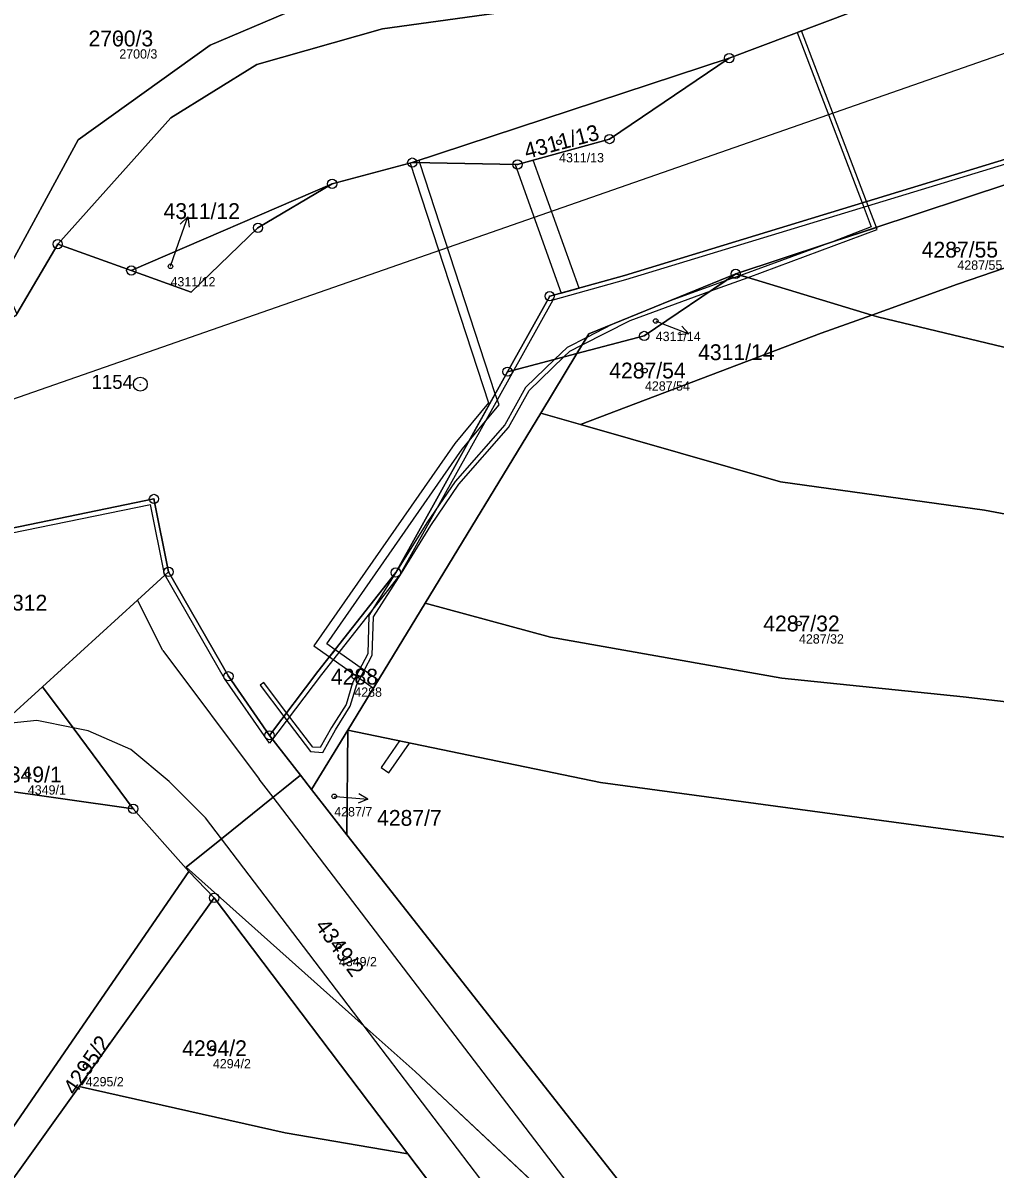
# Model space of a CAD drawing. Extents: x -739214 to -733252, y -1147612 to -1142842.
# Drawn here: x -737846.7 to -737742.2, y -1146463.6 to -1146340.4 of the extents above; entities that cross this region are included whole.
import ezdxf

# ---------------------------------------------------------------- set-up
doc = ezdxf.new("R2010")
doc.units = 0
for name, color, linetype in [('Definiční body', 7, 'Continuous'), ('Hranice parcel', 7, 'Continuous'), ('Parcelní čísla', 7, 'Continuous'), ('Polygon parcely', 7, 'Continuous'), ('Pop  PČ popisy', 7, 'Continuous'), ('Poz předměty', 7, 'Continuous'), ('Vnitřní kresba', 7, 'Continuous'), ('Věcná břemena k části', 7, 'Continuous'), ('Značky bodu BP', 7, 'Continuous')]:
    doc.layers.add(name, color=color, linetype=linetype)

msp = doc.modelspace()

# ---------------------------------------------------------------- linework, layer by layer
at = {"layer": 'Definiční body'}
for centre in [(-737836.38, -1146342.06), (-737789.07, -1146353.22), (-737746.22, -1146364.77), (-737830.87, -1146366.56), (-737778.67, -1146372.44), (-737779.83, -1146377.77), (-737763.26, -1146404.97), (-737811.1, -1146410.69), (-737846.22, -1146421.21), (-737813.26, -1146423.56), (-737812.76, -1146439.68), (-737826.31, -1146450.65), (-737839.99, -1146452.59)]:
    msp.add_circle(centre, 0.25, dxfattribs=at)
at = {"layer": 'Hranice parcel'}
for p, q in [((-737804.86, -1146355.41), (-737770.76, -1146344.17)), ((-737813.48, -1146357.69), (-737804.86, -1146355.41)), ((-737835.09, -1146367.01), (-737813.48, -1146357.69)), ((-737770.07, -1146367.38), (-737740.56, -1146357.63)), ((-737847.41, -1146371.67), (-737843.01, -1146364.17)), ((-737843.01, -1146364.17), (-737835.09, -1146367.01)), ((-737755.42, -1146371.8), (-737770.07, -1146367.38)), ((-737754.68, -1146372.02), (-737755.42, -1146371.8)), ((-737787.15, -1146375.94), (-737794.61, -1146377.89)), ((-737791.04, -1146382.34), (-737787.15, -1146375.94)), ((-737803.48, -1146402.77), (-737791.04, -1146382.34)), ((-737786.78, -1146383.56), (-737791.04, -1146382.34)), ((-737786.78, -1146383.56), (-737765.25, -1146389.72)), ((-737831.08, -1146399.42), (-737832.65, -1146391.58)), ((-737831.08, -1146399.42), (-737824.64, -1146410.65)), ((-737811.81, -1146416.45), (-737803.48, -1146402.77)), ((-737824.64, -1146410.65), (-737820.22, -1146417)), ((-737820.22, -1146417), (-737816.9, -1146421.29)), ((-737815.7, -1146422.84), (-737811.81, -1146416.45)), ((-737811.89, -1146427.69), (-737811.81, -1146416.45)), ((-737816.9, -1146421.29), (-737815.7, -1146422.84)), ((-737811.89, -1146427.69), (-737815.7, -1146422.84)), ((-737828.9, -1146431.66), (-737834.88, -1146424.9)), ((-737826.18, -1146434.48), (-737828.9, -1146431.66)), ((-737826.18, -1146434.48), (-737840.71, -1146454.78)), ((-737805.33, -1146462), (-737826.18, -1146434.48)), ((-737804.56, -1146453.15), (-737782.6, -1146473.73)), ((-737786.69, -1146486.61), (-737805.33, -1146462))]:
    msp.add_line(p, q, dxfattribs=at)
for points in [[(-737541.62, -1146282.04), (-737556.86, -1146290), (-737606.78, -1146309.22), (-737682.42, -1146335.31), (-737733.78, -1146352.83), (-737782.04, -1146367.55), (-737790.08, -1146369.77), (-737794.61, -1146377.89)], [(-737770.76, -1146344.17), (-737757.42, -1146339.15), (-737761.18, -1146335.83), (-737732.08, -1146310)], [(-737801.34, -1146332.03), (-737826.62, -1146342.79), (-737840.79, -1146352.96), (-737849.01, -1146368.07)], [(-737843.01, -1146364.17), (-737830.84, -1146350.59), (-737821.57, -1146344.85), (-737808.05, -1146341.01), (-737791.14, -1146338.69), (-737786.28, -1146336.05)], [(-737804.86, -1146355.41), (-737793.54, -1146355.61), (-737783.64, -1146352.87), (-737770.76, -1146344.17)], [(-737835.09, -1146367.01), (-737828.64, -1146369.33), (-737821.46, -1146362.41), (-737813.48, -1146357.69)], [(-737723.18, -1146360.59), (-737746.21, -1146368.48), (-737755.42, -1146371.8)], [(-737770.07, -1146367.38), (-737785.86, -1146373.83), (-737787.15, -1146375.94)], [(-737787.15, -1146375.94), (-737779.91, -1146374.05), (-737770.07, -1146367.38)], [(-737755.42, -1146371.8), (-737760.88, -1146373.76), (-737786.78, -1146383.56)], [(-737551.77, -1146412.44), (-737658.53, -1146391.6), (-737713.59, -1146381.89), (-737754.68, -1146372.02)], [(-737794.61, -1146377.89), (-737806.64, -1146399.5), (-737815.02, -1146410.14), (-737820.22, -1146417)], [(-737765.25, -1146389.72), (-737743.32, -1146392.8), (-737722.45, -1146396.68)], [(-737832.65, -1146391.58), (-737849.12, -1146394.96), (-737851.76, -1146395.5)], [(-737844.65, -1146411.77), (-737834.41, -1146402.45), (-737831.08, -1146399.42)], [(-737724.99, -1146415.27), (-737745.59, -1146412.86), (-737765.12, -1146410.86), (-737790, -1146406.44), (-737803.48, -1146402.77)], [(-737844.65, -1146411.77), (-737849.06, -1146415.79), (-737860.78, -1146426.46)], [(-737834.88, -1146424.9), (-737841.35, -1146416.2), (-737844.65, -1146411.77)], [(-737331.59, -1146506.62), (-737376.05, -1146494.4), (-737398.38, -1146490.12), (-737436.24, -1146484.9), (-737462.76, -1146481.83), (-737505.69, -1146475.14), (-737536.46, -1146468.45), (-737570.21, -1146459.63), (-737667.64, -1146439.85), (-737707.45, -1146432.51), (-737784.63, -1146422.07), (-737811.81, -1146416.45)], [(-737816.9, -1146421.29), (-737818.76, -1146422.79), (-737819.84, -1146423.66), (-737825.39, -1146428.13), (-737829.19, -1146431.19), (-737810.05, -1146448.26), (-737804.56, -1146453.15)], [(-737834.88, -1146424.9), (-737850.3, -1146422.72), (-737860.78, -1146426.46)], [(-737781.39, -1146466.64), (-737782.68, -1146464.89), (-737811.89, -1146427.69)], [(-737828.9, -1146431.66), (-737851.76, -1146464.79), (-737854.56, -1146467.91)], [(-737840.71, -1146454.78), (-737849.54, -1146467.11), (-737851.95, -1146469.79)], [(-737840.71, -1146454.78), (-737818.54, -1146459.73), (-737805.33, -1146462)]]:
    msp.add_lwpolyline(points, dxfattribs=at)
at = {"layer": 'Polygon parcely'}
for points in [[(-737851.76, -1146395.5), (-737849.12, -1146394.96), (-737832.65, -1146391.58), (-737831.08, -1146399.42), (-737824.64, -1146410.65), (-737820.22, -1146417), (-737815.02, -1146410.14), (-737806.64, -1146399.5), (-737794.61, -1146377.89), (-737790.08, -1146369.77), (-737782.04, -1146367.55), (-737733.78, -1146352.83), (-737682.42, -1146335.31), (-737606.78, -1146309.22), (-737556.86, -1146290), (-737541.62, -1146282.04), (-737519.96, -1146274.64), (-737515.86, -1146273.22), (-737508.96, -1146270.82), (-737487.35, -1146263.31), (-737469.84, -1146257.23), (-737448.4, -1146249.68), (-737443.72, -1146247.99)], [(-737733.73, -1146289.74), (-737746.11, -1146300.83), (-737747.42, -1146302), (-737757.62, -1146311.04), (-737758.73, -1146312.07), (-737772.14, -1146324.45), (-737773.11, -1146325.27), (-737785.1, -1146335.41), (-737786.28, -1146336.05), (-737791.14, -1146338.69), (-737808.05, -1146341.01), (-737821.57, -1146344.85), (-737830.84, -1146350.59), (-737843.01, -1146364.17), (-737835.09, -1146367.01), (-737813.48, -1146357.69), (-737804.86, -1146355.41), (-737770.76, -1146344.17), (-737757.42, -1146339.15), (-737761.18, -1146335.83), (-737732.08, -1146310)], [(-737732.08, -1146310), (-737761.18, -1146335.83), (-737757.42, -1146339.15), (-737770.76, -1146344.17), (-737783.64, -1146352.87), (-737793.54, -1146355.61), (-737804.86, -1146355.41), (-737813.48, -1146357.69), (-737821.46, -1146362.41), (-737828.64, -1146369.33), (-737835.09, -1146367.01), (-737843.01, -1146364.17), (-737847.41, -1146371.67), (-737847.53, -1146371.89), (-737858.37, -1146378.37), (-737869.23, -1146382.14), (-737887.99, -1146388.67), (-737903.08, -1146393.94), (-737917.17, -1146398.85), (-737950.33, -1146410.42), (-738012.69, -1146432)], [(-737782.6, -1146473.73), (-737804.56, -1146453.15), (-737810.05, -1146448.26), (-737829.19, -1146431.19), (-737825.39, -1146428.13), (-737819.84, -1146423.66), (-737818.76, -1146422.79), (-737816.9, -1146421.29), (-737820.22, -1146417), (-737824.64, -1146410.65), (-737831.08, -1146399.42), (-737834.41, -1146402.45), (-737844.65, -1146411.77), (-737841.35, -1146416.2), (-737834.88, -1146424.9), (-737828.9, -1146431.66), (-737826.18, -1146434.48), (-737805.33, -1146462), (-737786.69, -1146486.61)], [(-737601.76, -1146439.15), (-737682.84, -1146423.31), (-737724.99, -1146415.27), (-737745.59, -1146412.86), (-737765.12, -1146410.86), (-737790, -1146406.44), (-737803.48, -1146402.77), (-737811.81, -1146416.45), (-737784.63, -1146422.07), (-737707.45, -1146432.51), (-737667.64, -1146439.85), (-737570.21, -1146459.63)], [(-737570.21, -1146459.63), (-737667.64, -1146439.85), (-737707.45, -1146432.51), (-737784.63, -1146422.07), (-737811.81, -1146416.45), (-737811.89, -1146427.69), (-737782.68, -1146464.89), (-737781.39, -1146466.64), (-737745.1, -1146471.04), (-737711.25, -1146476.55), (-737674.41, -1146483.99), (-737637.16, -1146490.47), (-737547.67, -1146510.69)]]:
    msp.add_lwpolyline(points, dxfattribs=at)
for points in [[(-737684.38, -1146338.1), (-737655.7, -1146328.44), (-737626.81, -1146318.35), (-737600.2, -1146309.78), (-737577.46, -1146301.76), (-737556.74, -1146294.43), (-737552.17, -1146291.76), (-737537.24, -1146283.04), (-737541.62, -1146282.04), (-737556.86, -1146290), (-737606.78, -1146309.22), (-737682.42, -1146335.31), (-737733.78, -1146352.83), (-737782.04, -1146367.55), (-737790.08, -1146369.77), (-737794.61, -1146377.89), (-737787.15, -1146375.94), (-737785.86, -1146373.83), (-737770.07, -1146367.38), (-737740.56, -1146357.63)], [(-737827.22, -1146320.63), (-737843.12, -1146332.14), (-737851.48, -1146338.64), (-737854.77, -1146343.66), (-737852.92, -1146359.23), (-737849.01, -1146368.07), (-737840.79, -1146352.96), (-737826.62, -1146342.79), (-737801.34, -1146332.03), (-737824.03, -1146321.62)], [(-737808.05, -1146341.01), (-737791.14, -1146338.69), (-737786.28, -1146336.05), (-737801.34, -1146332.03), (-737826.62, -1146342.79), (-737840.79, -1146352.96), (-737849.01, -1146368.07), (-737847.41, -1146371.67), (-737843.01, -1146364.17), (-737830.84, -1146350.59), (-737821.57, -1146344.85)], [(-737793.54, -1146355.61), (-737783.64, -1146352.87), (-737770.76, -1146344.17), (-737804.86, -1146355.41)], [(-737821.46, -1146362.41), (-737813.48, -1146357.69), (-737835.09, -1146367.01), (-737828.64, -1146369.33)], [(-737723.18, -1146360.59), (-737740.56, -1146357.63), (-737770.07, -1146367.38), (-737755.42, -1146371.8), (-737746.21, -1146368.48)], [(-737396.69, -1146421.03), (-737448.36, -1146412.93), (-737497.86, -1146404.53), (-737562.89, -1146391.43), (-737675.19, -1146368.77), (-737723.18, -1146360.59), (-737746.21, -1146368.48), (-737755.42, -1146371.8), (-737754.68, -1146372.02), (-737713.59, -1146381.89), (-737658.53, -1146391.6), (-737551.77, -1146412.44), (-737511.77, -1146420.7), (-737456.17, -1146431.21), (-737379.73, -1146442.87), (-737361.98, -1146446.1), (-737309.41, -1146460.82), (-737300.2, -1146442.05), (-737343.52, -1146430.23), (-737371.91, -1146423.94)], [(-737755.42, -1146371.8), (-737770.07, -1146367.38), (-737779.91, -1146374.05), (-737787.15, -1146375.94), (-737791.04, -1146382.34), (-737786.78, -1146383.56), (-737760.88, -1146373.76)], [(-737770.07, -1146367.38), (-737785.86, -1146373.83), (-737787.15, -1146375.94), (-737779.91, -1146374.05)], [(-737755.42, -1146371.8), (-737760.88, -1146373.76), (-737786.78, -1146383.56), (-737765.25, -1146389.72), (-737743.32, -1146392.8), (-737722.45, -1146396.68), (-737709.82, -1146398.88), (-737687.3, -1146402.8), (-737628.45, -1146413.3), (-737553.62, -1146429.82), (-737551.77, -1146412.44), (-737658.53, -1146391.6), (-737713.59, -1146381.89), (-737754.68, -1146372.02)], [(-737791.04, -1146382.34), (-737787.15, -1146375.94), (-737794.61, -1146377.89), (-737806.64, -1146399.5), (-737815.02, -1146410.14), (-737820.22, -1146417), (-737816.9, -1146421.29), (-737815.7, -1146422.84), (-737811.81, -1146416.45), (-737803.48, -1146402.77)], [(-737786.78, -1146383.56), (-737791.04, -1146382.34), (-737803.48, -1146402.77), (-737790, -1146406.44), (-737765.12, -1146410.86), (-737745.59, -1146412.86), (-737724.99, -1146415.27), (-737722.45, -1146396.68), (-737743.32, -1146392.8), (-737765.25, -1146389.72)], [(-737849.12, -1146394.96), (-737851.76, -1146395.5), (-737856.82, -1146399.82), (-737861.62, -1146404.08), (-737875.13, -1146416.06), (-737881.78, -1146421.96), (-737884.7, -1146424.55), (-737913, -1146449.66), (-737944.75, -1146477.82), (-737952.78, -1146484.95), (-737946.83, -1146482.29), (-737945.21, -1146484.16), (-737939.52, -1146490.71), (-737937.64, -1146492.88), (-737940.02, -1146497.33), (-737921.27, -1146480.57), (-737883.72, -1146446.98), (-737860.78, -1146426.46), (-737849.06, -1146415.79), (-737844.65, -1146411.77), (-737834.41, -1146402.45), (-737831.08, -1146399.42), (-737832.65, -1146391.58)], [(-737841.35, -1146416.2), (-737844.65, -1146411.77), (-737849.06, -1146415.79), (-737860.78, -1146426.46), (-737850.3, -1146422.72), (-737834.88, -1146424.9)], [(-737811.81, -1146416.45), (-737815.7, -1146422.84), (-737811.89, -1146427.69)], [(-737818.76, -1146422.79), (-737819.84, -1146423.66), (-737825.39, -1146428.13), (-737829.19, -1146431.19), (-737810.05, -1146448.26), (-737804.56, -1146453.15), (-737782.6, -1146473.73), (-737775.4, -1146481.33), (-737768.05, -1146489.08), (-737742.17, -1146519.89), (-737765.45, -1146488.28), (-737781.39, -1146466.64), (-737782.68, -1146464.89), (-737811.89, -1146427.69), (-737815.7, -1146422.84), (-737816.9, -1146421.29)], [(-737834.88, -1146424.9), (-737850.3, -1146422.72), (-737860.78, -1146426.46), (-737883.72, -1146446.98), (-737854.56, -1146467.91), (-737851.76, -1146464.79), (-737828.9, -1146431.66)], [(-737854.56, -1146467.91), (-737851.95, -1146469.79), (-737849.54, -1146467.11), (-737840.71, -1146454.78), (-737826.18, -1146434.48), (-737828.9, -1146431.66), (-737851.76, -1146464.79)], [(-737805.33, -1146462), (-737826.18, -1146434.48), (-737840.71, -1146454.78), (-737818.54, -1146459.73)], [(-737812.09, -1146483.85), (-737786.69, -1146486.61), (-737805.33, -1146462), (-737818.54, -1146459.73), (-737840.71, -1146454.78), (-737849.54, -1146467.11), (-737851.95, -1146469.79), (-737839.88, -1146478.45)]]:
    msp.add_lwpolyline(points, close=True, dxfattribs=at)
at = {"layer": 'Pop  PČ popisy'}
for p, q in [((-737830, -1146364.08), (-737829.02, -1146361.24)), ((-737829.02, -1146361.24), (-737829.82, -1146362.03)), ((-737829.02, -1146361.24), (-737828.88, -1146362.35)), ((-737830.87, -1146366.56), (-737830, -1146364.08)), ((-737778.67, -1146372.44), (-737777.91, -1146372.74)), ((-737777.91, -1146372.74), (-737775.11, -1146373.81)), ((-737775.11, -1146373.81), (-737776.22, -1146373.92)), ((-737775.11, -1146373.81), (-737775.86, -1146372.99)), ((-737809.65, -1146423.88), (-737810.6, -1146423.29)), ((-737813.26, -1146423.56), (-737812.64, -1146423.62)), ((-737812.64, -1146423.62), (-737809.65, -1146423.88)), ((-737809.65, -1146423.88), (-737810.69, -1146424.29))]:
    msp.add_line(p, q, dxfattribs=at)
at = {"layer": 'Poz předměty'}
msp.add_line((-738196.39, -1146502.42), (-736812.26, -1146019.61), dxfattribs=at)
at = {"layer": 'Vnitřní kresba'}
for p, q in [((-737733.63, -1146353.31), (-737781.92, -1146368.03)), ((-737781.92, -1146368.03), (-737789.74, -1146370.19)), ((-737789.74, -1146370.19), (-737806.2, -1146399.74)), ((-737851.53, -1146395.97), (-737833.04, -1146392.17)), ((-737831.51, -1146399.67), (-737833.04, -1146392.17)), ((-737825.07, -1146410.9), (-737831.51, -1146399.67)), ((-737806.2, -1146399.74), (-737814.63, -1146410.45)), ((-737831.69, -1146407.89), (-737834.41, -1146402.45)), ((-737831.69, -1146407.89), (-737821.32, -1146421.72)), ((-737820.24, -1146417.85), (-737825.07, -1146410.9)), ((-737814.63, -1146410.45), (-737820.24, -1146417.85)), ((-737845.25, -1146415.41), (-737849.06, -1146415.79)), ((-737841.35, -1146416.2), (-737845.25, -1146415.41)), ((-737839.72, -1146416.53), (-737841.35, -1146416.2)), ((-737835.15, -1146418.52), (-737839.72, -1146416.53)), ((-737831, -1146421.98), (-737835.15, -1146418.52)), ((-737827.11, -1146425.87), (-737831, -1146421.98)), ((-737819.84, -1146423.66), (-737821.32, -1146421.72)), ((-737787.11, -1146466.48), (-737819.84, -1146423.66)), ((-737825.39, -1146428.13), (-737827.11, -1146425.87)), ((-737810.05, -1146448.26), (-737825.39, -1146428.13)), ((-737780.3, -1146487.28), (-737810.05, -1146448.26))]:
    msp.add_line(p, q, dxfattribs=at)
at = {"layer": 'Věcná břemena k části'}
for points in [[(-737756.46, -1146359.75), (-737755.98, -1146359.6), (-737763, -1146341.25), (-737763.47, -1146341.43)], [(-737805.08, -1146355.47), (-737796.65, -1146381.25), (-737800.28, -1146385.61), (-737815.46, -1146407.39), (-737813.78, -1146408.57), (-737813.17, -1146407.79), (-737814.07, -1146407.15), (-737799.48, -1146386.21), (-737798.76, -1146385.35), (-737795.93, -1146380.26), (-737804.05, -1146355.42), (-737804.13, -1146355.17), (-737804.86, -1146355.41)], [(-737786.92, -1146368.9), (-737791.84, -1146355.14), (-737793.54, -1146355.61), (-737793.79, -1146355.61), (-737788.85, -1146369.43)], [(-737755.98, -1146359.6), (-737756.46, -1146359.75), (-737755.48, -1146362.32), (-737759.64, -1146363.93), (-737754.91, -1146362.37)], [(-737754.91, -1146362.37), (-737759.64, -1146363.93), (-737769.55, -1146367.54), (-737768.73, -1146367.78), (-737754.84, -1146362.6)], [(-737772.74, -1146369.19), (-737768.73, -1146367.78), (-737769.55, -1146367.54), (-737771.11, -1146368.09)], [(-737786.59, -1146375.02), (-737781.41, -1146372.37), (-737772.74, -1146369.19), (-737771.11, -1146368.09), (-737777.24, -1146370.31), (-737783.39, -1146372.82), (-737786.09, -1146374.2)], [(-737814.76, -1146418.31), (-737815.55, -1146418.26), (-737818.38, -1146414.57), (-737818.69, -1146414.98), (-737815.81, -1146418.74), (-737814.48, -1146418.83), (-737813.13, -1146416.41), (-737811.53, -1146413.88), (-737810.82, -1146411.53), (-737809.16, -1146408.39), (-737809.02, -1146404.27), (-737806.01, -1146399.57), (-737802.88, -1146394.42), (-737799.86, -1146390), (-737794.51, -1146383.88), (-737792.27, -1146379.9), (-737788.54, -1146376.3), (-737787.91, -1146375.7), (-737786.59, -1146375.02), (-737786.09, -1146374.2), (-737788.21, -1146375.28), (-737789.53, -1146376.56), (-737792.67, -1146379.59), (-737794.92, -1146383.59), (-737800.26, -1146389.7), (-737803.3, -1146394.15), (-737806.64, -1146399.5), (-737809.52, -1146404.11), (-737809.66, -1146408.25), (-737811.28, -1146411.34), (-737811.99, -1146413.67), (-737813.56, -1146416.15)], [(-737798.76, -1146385.35), (-737795.53, -1146381.47), (-737795.93, -1146380.26)], [(-737813.78, -1146408.57), (-737809.04, -1146411.91), (-737808.53, -1146411.06), (-737813.17, -1146407.79)], [(-737821.24, -1146411.61), (-737818.69, -1146414.98), (-737818.38, -1146414.57), (-737820.84, -1146411.31)], [(-737806.22, -1146417.6), (-737808.21, -1146420.46), (-737807.38, -1146421.03), (-737805.16, -1146417.83)]]:
    msp.add_lwpolyline(points, close=True, dxfattribs=at)
at = {"layer": 'Značky bodu BP'}
for centre, radius in [((-737770.76, -1146344.17), 0.5), ((-737770.76, -1146344.17), 0.0303), ((-737783.64, -1146352.87), 0.5), ((-737783.64, -1146352.87), 0.0303), ((-737804.86, -1146355.41), 0.5), ((-737804.86, -1146355.41), 0.0303), ((-737793.54, -1146355.61), 0.5), ((-737793.54, -1146355.61), 0.0303), ((-737813.48, -1146357.69), 0.5), ((-737813.48, -1146357.69), 0.0303), ((-737821.46, -1146362.41), 0.5), ((-737821.46, -1146362.41), 0.0303), ((-737843.01, -1146364.17), 0.5), ((-737843.01, -1146364.17), 0.0303), ((-737835.09, -1146367.01), 0.5), ((-737835.09, -1146367.01), 0.0303), ((-737770.07, -1146367.38), 0.5), ((-737770.07, -1146367.38), 0.0303), ((-737790.08, -1146369.77), 0.5), ((-737790.08, -1146369.77), 0.0303), ((-737779.91, -1146374.05), 0.5), ((-737779.91, -1146374.05), 0.0303), ((-737794.61, -1146377.89), 0.5), ((-737834.12, -1146379.24), 0.75), ((-737794.61, -1146377.89), 0.0303), ((-737834.12, -1146379.24), 0.03), ((-737832.65, -1146391.58), 0.5), ((-737832.65, -1146391.58), 0.0303), ((-737831.08, -1146399.42), 0.5), ((-737831.08, -1146399.42), 0.0303), ((-737806.64, -1146399.5), 0.5), ((-737806.64, -1146399.5), 0.0303), ((-737824.64, -1146410.65), 0.5), ((-737824.64, -1146410.65), 0.0303), ((-737820.22, -1146417), 0.5), ((-737820.22, -1146417), 0.0303), ((-737834.88, -1146424.9), 0.5), ((-737834.88, -1146424.9), 0.0303), ((-737826.18, -1146434.48), 0.5), ((-737826.18, -1146434.48), 0.0303)]:
    msp.add_circle(centre, radius, dxfattribs=at)

# ---------------------------------------------------------------- texts
at = {"layer": 'Definiční body'}
for s, p in [('2700/3', (-737836.38, -1146344.22)), ('4311/13', (-737789.07, -1146355.38)), ('4287/55', (-737746.22, -1146366.93)), ('4311/12', (-737830.87, -1146368.72)), ('4311/14', (-737778.67, -1146374.6)), ('4287/54', (-737779.83, -1146379.93)), ('4287/32', (-737763.26, -1146407.13)), ('4288', (-737811.1, -1146412.85)), ('4349/1', (-737846.22, -1146423.37)), ('4287/7', (-737813.26, -1146425.72)), ('4349/2', (-737812.76, -1146441.84)), ('4294/2', (-737826.31, -1146452.81)), ('4295/2', (-737839.99, -1146454.75))]:
    msp.add_text(s, height=1, dxfattribs=at).set_placement(p)
at = {"layer": 'Parcelní čísla'}
for s, p in [('2700/3', (-737839.69, -1146342.91)), ('4311/12', (-737831.62, -1146361.47)), ('4287/55', (-737750.06, -1146365.62)), ('4311/14', (-737774.11, -1146376.65)), ('4287/54', (-737783.67, -1146378.62)), ('4312', (-737849.19, -1146403.58)), ('4287/32', (-737767.1, -1146405.82)), ('4288', (-737813.61, -1146411.54)), ('4349/1', (-737849.53, -1146422.06)), ('4287/7', (-737808.65, -1146426.73)), ('4294/2', (-737829.61, -1146451.5))]:
    msp.add_text(s, height=1.7, dxfattribs=at).set_placement(p)
for s, rotation, p in [('4311/13', 15, (-737792.56, -1146355.03)), ('4349/2', 306, (-737815.39, -1146437.51)), ('4295/2', 56, (-737841.13, -1146455.8))]:
    msp.add_text(s, height=1.7, rotation=rotation, dxfattribs=at).set_placement(p)
at = {"layer": 'Značky bodu BP'}
msp.add_text('1154', height=1.5, dxfattribs=at).set_placement((-737839.37, -1146379.74))

doc.saveas('drawing.dxf')
